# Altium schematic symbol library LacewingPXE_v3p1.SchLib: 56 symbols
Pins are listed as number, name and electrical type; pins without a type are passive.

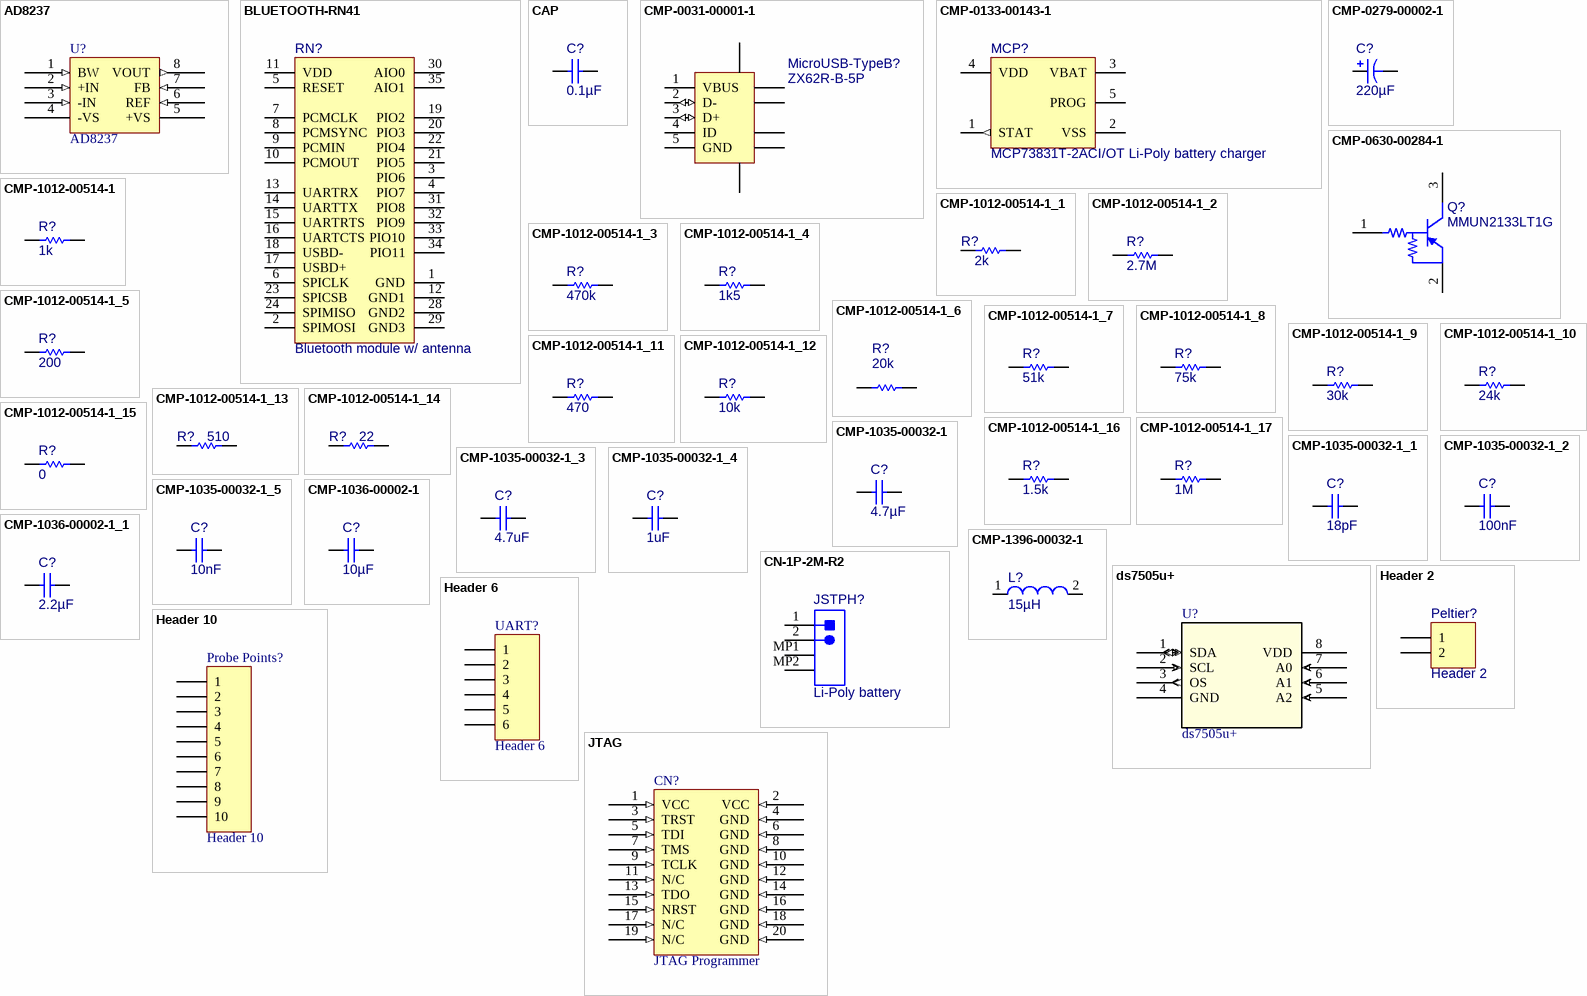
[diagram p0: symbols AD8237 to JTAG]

## AD8237
designator U?
footprint ADI-RM-8_N (SOP, 8-Leads, Body 3x3mm, Pitch 0.65mm, IPC Medium Density)
pins: 1 BW (in), 2 +IN (in), 3 -IN (in), 4 -VS (power), 5 +VS (power), 6 REF (in), 7 FB (in), 8 VOUT (out)

## BLUETOOTH-RN41
designator RN?, comment Bluetooth module w/ antenna
Bluetooth SMD module
footprint RN41
pins: 1 GND, 2 SPIMOSI, 3 PIO6, 4 PIO7, 5 RESET, 6 SPICLK, 7 PCMCLK, 8 PCMSYNC, 9 PCMIN, 10 PCMOUT, 11 VDD, 12 GND1, 13 UARTRX, 14 UARTTX, 15 UARTRTS, 16 UARTCTS, 17 USBD+, 18 USBD-, 19 PIO2, 20 PIO3, 21 PIO5, 22 PIO4, 23 SPICSB, 24 SPIMISO, 28 GND2, 29 GND3, 30 AIO0, 31 PIO8, 32 PIO9, 33 PIO10, 34 PIO11, 35 AIO1

## CAP
designator C?, comment 0.1µF
Ceramic CAP0603 (1608 Metric) Thickness 1mm SMD; Case-EIA: 0603
footprint CAPC0603(1608)100_N (Chip Capacitor, Body 1.6x0.8mm, Height 1.0mm, IPC Medium Density)
pins: 1, 2
1 alternate drawing of the same symbol

## CMP-0031-00001-1
designator MicroUSB-TypeB?, comment ZX62R-B-5P
Connector; USBMicro-B,Reverse type, SMT; 5 Position; Right Angle
footprint HIRO-ZX62R-B-5P_V (USB Micro-B R/A Connector)
pins: 1 VBUS (power), 2 D- (io), 3 D+ (io), 4 ID, 5 GND (power), 6 SHLD, 7 SHLD, 8 SHLD, 9 SHLD, 10 SHLD, 11 SHLD

## CMP-0133-00143-1
designator MCP?, comment MCP73831T-2ACI/OT Li-Poly battery charger
Miniature Single-Cell, Fully Integrated Li-Ion, Li-Polymer Charge Management Controller, 4.2V, 5-Pin SOT-23, Industrial Temperature, Tape and Reel
footprint SOT-23-OT5_M (SOT23, 5-Leads, Body 2.9x1.6mm, Pitch 0.95mm, Lead Span 2.7mm, IPC Low Density)
footprint SOT-23-OT5_L (SOT23, 5-Leads, Body 2.9x1.6mm, Pitch 0.95mm, Lead Span 2.7mm, IPC High Density)
footprint SOT-23-OT5_N (SOT23, 5-Leads, Body 2.9x1.6mm, Pitch 0.95mm, Lead Span 2.7mm, IPC Medium Density)
pins: 1 STAT (out), 2 VSS (power), 3 VBAT (power), 4 VDD (power), 5 PROG

## CMP-0279-00002-1
designator C?, comment 220µF
Capacitor, Tantalum, 220uF 10% 10V MCCT-D (7343-31); PartNumber: TAJD227K010R; Manufacturer: AVX; Polarity: Polarized
footprint AVX-CAPC7343_V (SMT Capacitor, 2 Leads, Body 7.3x4.3mm)
pins: 1, 2

## CMP-0630-00284-1
designator Q?, comment MMUN2133LT1G
Digital Transistor (BRT), R1=4.7 kOhm, R2=47 kOhm, PNP Transistor, 3-Pin SOT-23, Pb-Free, Tape and Reel
footprint ONSC-SOT-23-3-318-08_V (SOT23, 3-Leads, Body 2.92x1.3mm, Pitch 0.95mm)
pins: 1 B, 2 E, 3 C

## CMP-1012-00514-1
designator R?, comment 1k
RES0603 (1608 Metric)  SMD; Case-EIA: 0603
footprint RESC0603(1608)_N (Chip Resistor, Body 1.6x0.8mm, IPC Medium Density)
footprint RESC0603(1608)_M (Chip Resistor, Body 1.6x0.8mm, IPC Low Density)
footprint RESC0603(1608)_L (Chip Resistor, Body 1.6x0.8mm, IPC High Density)
pins: 1, 2
1 alternate drawing of the same symbol

## CMP-1012-00514-1_1
designator R?, comment 2k
RES0603 (1608 Metric)  SMD; Case-EIA: 0603
footprint RESC0603(1608)_N (Chip Resistor, Body 1.6x0.8mm, IPC Medium Density)
footprint RESC0603(1608)_M (Chip Resistor, Body 1.6x0.8mm, IPC Low Density)
footprint RESC0603(1608)_L (Chip Resistor, Body 1.6x0.8mm, IPC High Density)
pins: 1, 2
1 alternate drawing of the same symbol

## CMP-1012-00514-1_2
designator R?, comment 2.7M
RES0603 (1608 Metric)  SMD; Case-EIA: 0603
footprint RESC0603(1608)_N (Chip Resistor, Body 1.6x0.8mm, IPC Medium Density)
footprint RESC0603(1608)_M (Chip Resistor, Body 1.6x0.8mm, IPC Low Density)
footprint RESC0603(1608)_L (Chip Resistor, Body 1.6x0.8mm, IPC High Density)
pins: 1, 2
1 alternate drawing of the same symbol

## CMP-1012-00514-1_3
designator R?, comment 470k
RES0603 (1608 Metric)  SMD; Case-EIA: 0603
footprint RESC0603(1608)_N (Chip Resistor, Body 1.6x0.8mm, IPC Medium Density)
footprint RESC0603(1608)_M (Chip Resistor, Body 1.6x0.8mm, IPC Low Density)
footprint RESC0603(1608)_L (Chip Resistor, Body 1.6x0.8mm, IPC High Density)
pins: 1, 2
1 alternate drawing of the same symbol

## CMP-1012-00514-1_4
designator R?, comment 1k5
RES0603 (1608 Metric)  SMD; Case-EIA: 0603
footprint RESC0603(1608)_N (Chip Resistor, Body 1.6x0.8mm, IPC Medium Density)
footprint RESC0603(1608)_M (Chip Resistor, Body 1.6x0.8mm, IPC Low Density)
footprint RESC0603(1608)_L (Chip Resistor, Body 1.6x0.8mm, IPC High Density)
pins: 1, 2
1 alternate drawing of the same symbol

## CMP-1012-00514-1_5
designator R?, comment 200
RES0603 (1608 Metric)  SMD; Case-EIA: 0603
footprint RESC0603(1608)_N (Chip Resistor, Body 1.6x0.8mm, IPC Medium Density)
footprint RESC0603(1608)_M (Chip Resistor, Body 1.6x0.8mm, IPC Low Density)
footprint RESC0603(1608)_L (Chip Resistor, Body 1.6x0.8mm, IPC High Density)
pins: 1, 2
1 alternate drawing of the same symbol

## CMP-1012-00514-1_6
designator R?, comment 20k
RES0603 (1608 Metric)  SMD; Case-EIA: 0603
footprint RESC0603(1608)_N (Chip Resistor, Body 1.6x0.8mm, IPC Medium Density)
footprint RESC0603(1608)_M (Chip Resistor, Body 1.6x0.8mm, IPC Low Density)
footprint RESC0603(1608)_L (Chip Resistor, Body 1.6x0.8mm, IPC High Density)
pins: 1, 2
1 alternate drawing of the same symbol

## CMP-1012-00514-1_7
designator R?, comment 51k
RES0603 (1608 Metric)  SMD; Case-EIA: 0603
footprint RESC0603(1608)_N (Chip Resistor, Body 1.6x0.8mm, IPC Medium Density)
footprint RESC0603(1608)_M (Chip Resistor, Body 1.6x0.8mm, IPC Low Density)
footprint RESC0603(1608)_L (Chip Resistor, Body 1.6x0.8mm, IPC High Density)
pins: 1, 2
1 alternate drawing of the same symbol

## CMP-1012-00514-1_8
designator R?, comment 75k
RES0603 (1608 Metric)  SMD; Case-EIA: 0603
footprint RESC0603(1608)_N (Chip Resistor, Body 1.6x0.8mm, IPC Medium Density)
footprint RESC0603(1608)_M (Chip Resistor, Body 1.6x0.8mm, IPC Low Density)
footprint RESC0603(1608)_L (Chip Resistor, Body 1.6x0.8mm, IPC High Density)
pins: 1, 2
1 alternate drawing of the same symbol

## CMP-1012-00514-1_9
designator R?, comment 30k
RES0603 (1608 Metric)  SMD; Case-EIA: 0603
footprint RESC0603(1608)_N (Chip Resistor, Body 1.6x0.8mm, IPC Medium Density)
footprint RESC0603(1608)_M (Chip Resistor, Body 1.6x0.8mm, IPC Low Density)
footprint RESC0603(1608)_L (Chip Resistor, Body 1.6x0.8mm, IPC High Density)
pins: 1, 2
1 alternate drawing of the same symbol

## CMP-1012-00514-1_10
designator R?, comment 24k
RES0603 (1608 Metric)  SMD; Case-EIA: 0603
footprint RESC0603(1608)_N (Chip Resistor, Body 1.6x0.8mm, IPC Medium Density)
footprint RESC0603(1608)_M (Chip Resistor, Body 1.6x0.8mm, IPC Low Density)
footprint RESC0603(1608)_L (Chip Resistor, Body 1.6x0.8mm, IPC High Density)
pins: 1, 2
1 alternate drawing of the same symbol

## CMP-1012-00514-1_11
designator R?, comment 470
RES0603 (1608 Metric)  SMD; Case-EIA: 0603
footprint RESC0603(1608)_N (Chip Resistor, Body 1.6x0.8mm, IPC Medium Density)
footprint RESC0603(1608)_M (Chip Resistor, Body 1.6x0.8mm, IPC Low Density)
footprint RESC0603(1608)_L (Chip Resistor, Body 1.6x0.8mm, IPC High Density)
pins: 1, 2
1 alternate drawing of the same symbol

## CMP-1012-00514-1_12
designator R?, comment 10k
RES0603 (1608 Metric)  SMD; Case-EIA: 0603
footprint RESC0603(1608)_N (Chip Resistor, Body 1.6x0.8mm, IPC Medium Density)
footprint RESC0603(1608)_M (Chip Resistor, Body 1.6x0.8mm, IPC Low Density)
footprint RESC0603(1608)_L (Chip Resistor, Body 1.6x0.8mm, IPC High Density)
pins: 1, 2
1 alternate drawing of the same symbol

## CMP-1012-00514-1_13
designator R?, comment 510
RES0603 (1608 Metric)  SMD; Case-EIA: 0603
footprint RESC0603(1608)_N (Chip Resistor, Body 1.6x0.8mm, IPC Medium Density)
footprint RESC0603(1608)_M (Chip Resistor, Body 1.6x0.8mm, IPC Low Density)
footprint RESC0603(1608)_L (Chip Resistor, Body 1.6x0.8mm, IPC High Density)
pins: 1, 2
1 alternate drawing of the same symbol

## CMP-1012-00514-1_14
designator R?, comment 22
RES0603 (1608 Metric)  SMD; Case-EIA: 0603
footprint RESC0603(1608)_N (Chip Resistor, Body 1.6x0.8mm, IPC Medium Density)
footprint RESC0603(1608)_M (Chip Resistor, Body 1.6x0.8mm, IPC Low Density)
footprint RESC0603(1608)_L (Chip Resistor, Body 1.6x0.8mm, IPC High Density)
pins: 1, 2
1 alternate drawing of the same symbol

## CMP-1012-00514-1_15
designator R?, comment 0
RES0603 (1608 Metric)  SMD; Case-EIA: 0603
footprint RESC0603(1608)_N (Chip Resistor, Body 1.6x0.8mm, IPC Medium Density)
footprint RESC0603(1608)_M (Chip Resistor, Body 1.6x0.8mm, IPC Low Density)
footprint RESC0603(1608)_L (Chip Resistor, Body 1.6x0.8mm, IPC High Density)
pins: 1, 2
1 alternate drawing of the same symbol

## CMP-1012-00514-1_16
designator R?, comment 1.5k
RES0603 (1608 Metric)  SMD; Case-EIA: 0603
footprint RESC0603(1608)_N (Chip Resistor, Body 1.6x0.8mm, IPC Medium Density)
footprint RESC0603(1608)_M (Chip Resistor, Body 1.6x0.8mm, IPC Low Density)
footprint RESC0603(1608)_L (Chip Resistor, Body 1.6x0.8mm, IPC High Density)
pins: 1, 2
1 alternate drawing of the same symbol

## CMP-1012-00514-1_17
designator R?, comment 1M
RES0603 (1608 Metric)  SMD; Case-EIA: 0603
footprint RESC0603(1608)_N (Chip Resistor, Body 1.6x0.8mm, IPC Medium Density)
footprint RESC0603(1608)_M (Chip Resistor, Body 1.6x0.8mm, IPC Low Density)
footprint RESC0603(1608)_L (Chip Resistor, Body 1.6x0.8mm, IPC High Density)
pins: 1, 2
1 alternate drawing of the same symbol

## CMP-1035-00032-1
designator C?, comment 4.7µF
Ceramic CAP0603 (1608 Metric) Thickness 1mm SMD; Case-EIA: 0603; Rated Voltage: 10 V
footprint CAPC0603(1608)100_N (Chip Capacitor, Body 1.6x0.8mm, Height 1.0mm, IPC Medium Density)
footprint CAPC0603(1608)100_L (Chip Capacitor, Body 1.6x0.8mm, Height 1.0mm, IPC High Density)
footprint CAPC0603(1608)100_M (Chip Capacitor, Body 1.6x0.8mm, Height 1.0mm, IPC Low Density)
pins: 1, 2
1 alternate drawing of the same symbol

## CMP-1035-00032-1_1
designator C?, comment 18pF
Ceramic CAP0603 (1608 Metric) Thickness 1mm SMD; Case-EIA: 0603
footprint CAPC0603(1608)100_N (Chip Capacitor, Body 1.6x0.8mm, Height 1.0mm, IPC Medium Density)
footprint CAPC0603(1608)100_L (Chip Capacitor, Body 1.6x0.8mm, Height 1.0mm, IPC High Density)
footprint CAPC0603(1608)100_M (Chip Capacitor, Body 1.6x0.8mm, Height 1.0mm, IPC Low Density)
pins: 1, 2
1 alternate drawing of the same symbol

## CMP-1035-00032-1_2
designator C?, comment 100nF
Ceramic CAP0603 (1608 Metric) Thickness 1mm SMD; Case-EIA: 0603
footprint CAPC0603(1608)100_N (Chip Capacitor, Body 1.6x0.8mm, Height 1.0mm, IPC Medium Density)
footprint CAPC0603(1608)100_L (Chip Capacitor, Body 1.6x0.8mm, Height 1.0mm, IPC High Density)
footprint CAPC0603(1608)100_M (Chip Capacitor, Body 1.6x0.8mm, Height 1.0mm, IPC Low Density)
pins: 1, 2
1 alternate drawing of the same symbol

## CMP-1035-00032-1_3
designator C?, comment 4.7uF
Ceramic CAP0603 (1608 Metric) Thickness 1mm SMD; Case-EIA: 0603
footprint CAPC0603(1608)100_N (Chip Capacitor, Body 1.6x0.8mm, Height 1.0mm, IPC Medium Density)
footprint CAPC0603(1608)100_L (Chip Capacitor, Body 1.6x0.8mm, Height 1.0mm, IPC High Density)
footprint CAPC0603(1608)100_M (Chip Capacitor, Body 1.6x0.8mm, Height 1.0mm, IPC Low Density)
pins: 1, 2
1 alternate drawing of the same symbol

## CMP-1035-00032-1_4
designator C?, comment 1uF
Ceramic CAP0603 (1608 Metric) Thickness 1mm SMD; Case-EIA: 0603
footprint CAPC0603(1608)100_N (Chip Capacitor, Body 1.6x0.8mm, Height 1.0mm, IPC Medium Density)
footprint CAPC0603(1608)100_L (Chip Capacitor, Body 1.6x0.8mm, Height 1.0mm, IPC High Density)
footprint CAPC0603(1608)100_M (Chip Capacitor, Body 1.6x0.8mm, Height 1.0mm, IPC Low Density)
pins: 1, 2
1 alternate drawing of the same symbol

## CMP-1035-00032-1_5
designator C?, comment 10nF
Ceramic CAP0603 (1608 Metric) Thickness 1mm SMD; Case-EIA: 0603
footprint CAPC0603(1608)100_N (Chip Capacitor, Body 1.6x0.8mm, Height 1.0mm, IPC Medium Density)
footprint CAPC0603(1608)100_L (Chip Capacitor, Body 1.6x0.8mm, Height 1.0mm, IPC High Density)
footprint CAPC0603(1608)100_M (Chip Capacitor, Body 1.6x0.8mm, Height 1.0mm, IPC Low Density)
pins: 1, 2
1 alternate drawing of the same symbol

## CMP-1036-00002-1
designator C?, comment 10µF
Ceramic CAP0805 (2012 Metric) Thickness 0.75mm SMD; Case-EIA: 0805; Rated Voltage: 10 V
footprint CAPC0805(2012)75_N (Chip Capacitor, Body 2.0x1.2mm, Height 0.75mm, IPC Medium Density)
footprint CAPC0805(2012)75_L (Chip Capacitor, Body 2.0x1.2mm, Height 0.75mm, IPC High Density)
footprint CAPC0805(2012)75_M (Chip Capacitor, Body 2.0x1.2mm, Height 0.75mm, IPC Low Density)
pins: 1, 2
1 alternate drawing of the same symbol

## CMP-1036-00002-1_1
designator C?, comment 2.2µF
Ceramic CAP0805 (2012 Metric) Thickness 0.75mm SMD; Case-EIA: 0805; Rated Voltage: 10 V
footprint CAPC0805(2012)75_N (Chip Capacitor, Body 2.0x1.2mm, Height 0.75mm, IPC Medium Density)
footprint CAPC0805(2012)75_L (Chip Capacitor, Body 2.0x1.2mm, Height 0.75mm, IPC High Density)
footprint CAPC0805(2012)75_M (Chip Capacitor, Body 2.0x1.2mm, Height 0.75mm, IPC Low Density)
pins: 1, 2
1 alternate drawing of the same symbol

## CMP-1396-00032-1
designator L?, comment 15µH
SMD-Shielded Power Inductor WE-PD 7447714150, L=15 µH
footprint WE-PD 1050 (SMD Inductor, 2-Leads, Body 10,0x10,0mm)
pins: 1, 2

## CN-1P-2M-R2
designator JSTPH?, comment Li-Poly battery
JST PH 2-pin 2-holder SMD
footprint JST- S2B-PH-SM4-TB(LF)(SN)-2_V (SMD, 2-Leads, Body 7.9x7.6mm, Pitch 2mm)
footprint JST- S2B-PH-SM4-TB(LF)(SN)-2_V (SMD, 2-Leads, Body 7.9x7.6mm, Pitch 2mm)
footprint JST- S2B-PH-SM4-TB(LF)(SN)-2_V (SMD, 2-Leads, Body 7.9x7.6mm, Pitch 2mm)
pins: 1, 2, MP1, MP2

## ds7505u+
designator U?
No Description Available; Vendor: Maxim Integrated Products; Built_By: EMA_UL_Team
footprint 21-0036K
pins: 1 SDA (io), 2 SCL (in), 3 OS (out), 4 GND (power), 5 A2 (in), 6 A1 (in), 7 A0 (in), 8 VDD (power)

## Header 2
designator Peltier?
Header, 2-Pin
footprint HDR1X2 (Connector; Header; 2 Position)
pins: 1, 2

## Header 6
designator UART?
Header, 6-Pin
footprint HDR1X6 (Connector; Header; 6 Position)
signal-integrity model Connector
pins: 1, 2, 3, 4, 5, 6

## Header 10
designator Probe Points?
Header, 10-Pin
footprint HDR1X10 (Connector; Header; 10 Position)
signal-integrity model Connector
pins: 1, 2, 3, 4, 5, 6, 7, 8, 9, 10

## JTAG
designator CN?, comment JTAG Programmer
footprint JTAG (Connector; 20 pin)
footprint JTAG2 (Header, Vertical Shrouded, 100 mil pitch; 25 mil lead width, 20 pins, 2 rows, 10 pins per row, 1295 mil L X 346 mil W X 346 mil H body)
pins: 1 VCC (in), 2 VCC (in), 3 TRST (in), 4 GND (in), 5 TDI (in), 6 GND (in), 7 TMS (in), 8 GND (in), 9 TCLK (in), 10 GND (in), 11 N/C (in), 12 GND (in), 13 TDO (in), 14 GND (in), 15 NRST (in), 16 GND (in), 17 N/C (in), 18 GND (in), 19 N/C (in), 20 GND (in)

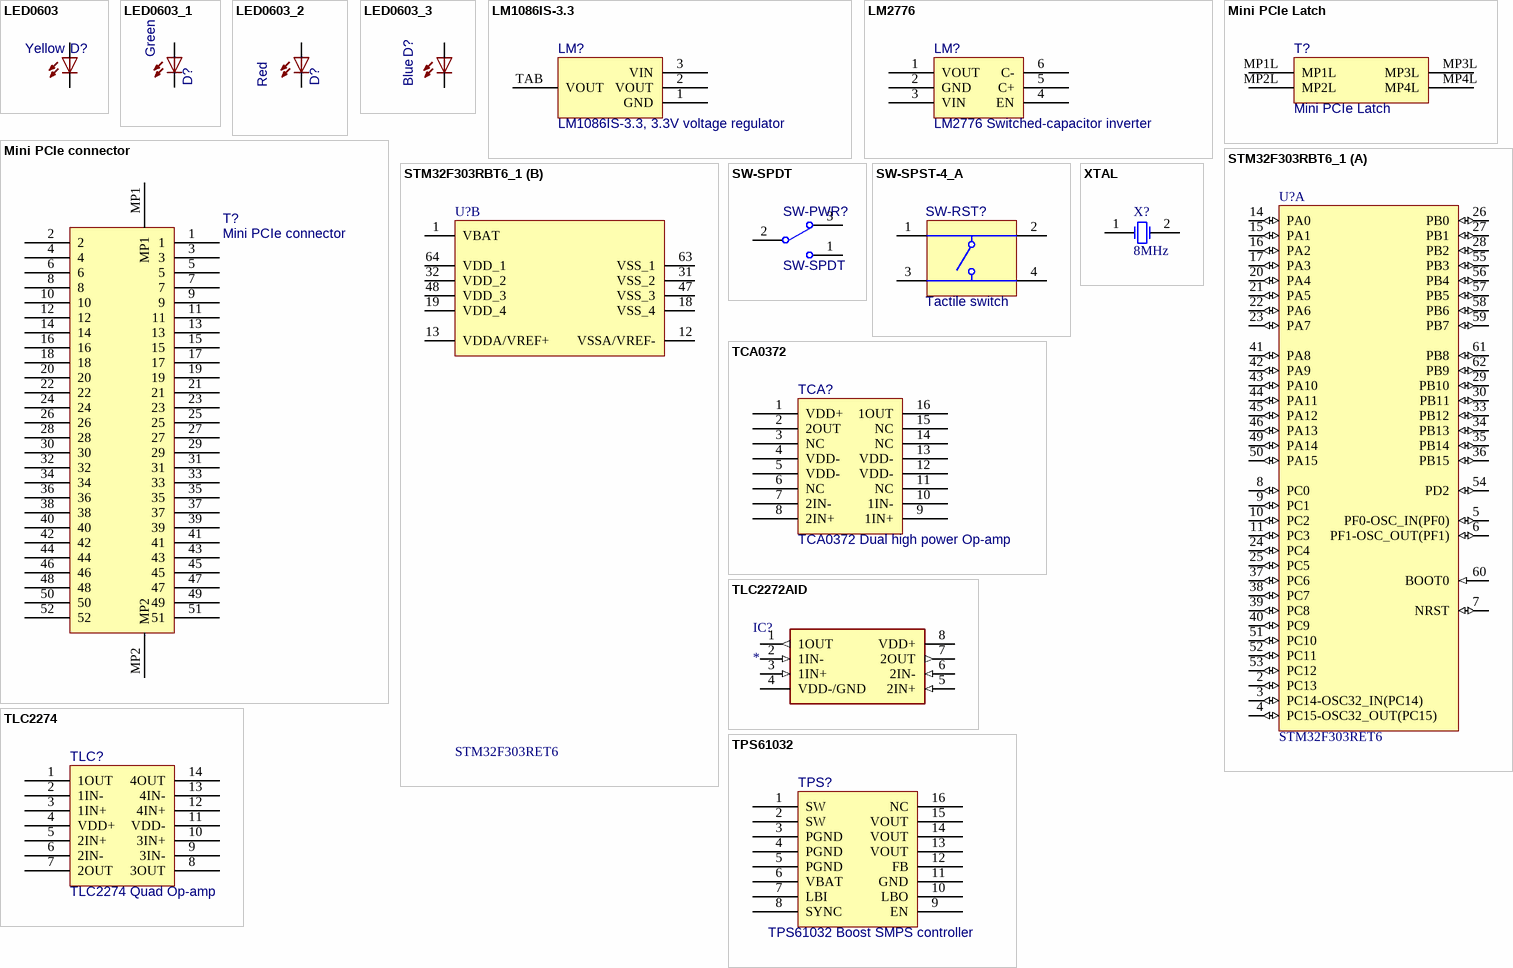
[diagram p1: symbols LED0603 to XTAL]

## LED0603
designator D?, comment Yellow
LED SMD 0603
footprint LED-0603
pins: A, C

## LED0603_1
designator D?, comment Green
LED SMD 0603
footprint LED-0603
pins: A, C

## LED0603_2
designator D?, comment Red
LED SMD 0603
footprint LED-0603
pins: A, C

## LED0603_3
designator D?, comment Blue
LED SMD 0603; RS Order: 654-5666
footprint LED-0603
pins: A, C

## LM1086IS-3.3
designator LM?, comment LM1086IS-3.3, 3.3V voltage regulator
footprint TS3B_M (D2-PAK, 4-Leads, Body 8.6x10.2mm, Pitch 2.54mm, Lead Span 14.2mm, IPC Low Density)
pins: 1 GND, 2 VOUT, 3 VIN, TAB VOUT

## LM2776
designator LM?, comment LM2776 Switched-capacitor inverter
footprint TI-DBV6_M (SOT-23, 6-Leads, Body 2.90x1.60mm, Pitch 0.95mm, IPC Low Density)
pins: 1 VOUT, 2 GND, 3 VIN, 4 EN, 5 C+, 6 C-

## Mini PCIe connector
designator T?
footprint Molex Conn-67910 (Board-to-Board Connector, SMT, Right Angle, Pitch 0.8mm, 52-Position, Female)
pins: 1, 2, 3, 4, 5, 6, 7, 8, 9, 10, 11, 12, 13, 14, 15, 16, 17, 18, 19, 20, 21, 22, 23, 24, 25, 26, 27, 28, 29, 30, 31, 32, 33, 34, 35, 36, 37, 38, 39, 40, 41, 42, 43, 44, 45, 46, 47, 48, 49, 50, 51, 52, MP1, MP2

## Mini PCIe Latch
designator T?
footprint Molex Latch-48099
pins: MP1L, MP2L, MP3L, MP4L

## STM32F303RBT6_1
designator U?, comment STM32F303RET6
ARM Cortex-M4 32-bit MCU, 128 KB Flash, 32 KB Internal RAM, 52 I/Os, 64-pin LQFP, -40 to 85 degC, Tray; PartNumber: STM32F303RBT6; D/A Converter: 2x12-bit (2 Channel); FLASH Size (Prog) (kB): 128; I/Os (High Current): 52; Internal RAM Size (kB): 32; Operating Frequency(F) (Processor speed) (MHz): 72; Supply Voltage(Vcc) min (V): 2
footprint STM-LQFP64_N (Thin QFP, 64-Leads, Body 10x10mm, Pitch 0.5mm, IPC Medium Density)
footprint STM-LQFP64_L (Thin QFP, 64-Leads, Body 10x10mm, Pitch 0.5mm, IPC High Density)
footprint STM-LQFP64_M (Thin QFP, 64-Leads, Body 10x10mm, Pitch 0.5mm, IPC Low Density)
footprint STM-LQFP64_V (Thin QFP, 64-Leads, Body 10x10mm, Pitch 0.5mm, ST Recommended)
part A pins: 2 PC13 (io) "PC13/TIM1_CH1N/WKUP2,RTC_TAMP1,RTC_TS,RTC_OUT", 3 PC14-OSC32_IN(PC14) (io) "PC14-OSC32_IN(PC14)/OSC32_IN", 4 PC15-OSC32_OUT(PC15) (io) "PC15-OSC32_OUT(PC15)/OSC32_OUT", 5 PF0-OSC_IN(PF0) (io) "PF0-OSC_IN(PF0)/TIM1_CH3N,I2C2_SDA/OSC_IN", 6 PF1-OSC_OUT(PF1) (io) "PF1-OSC_OUT(PF1)/I2C2_SCL/OSC_OUT", 7 NRST (io) "Device reset input / internal reset output (active low)", 8 PC0 (io) "PC0/EVENTOUT/ADC12_IN6,COMP7_INM", 9 PC1 (io) "PC1/EVENTOUT/ADC12_IN7,COMP7_INP", 10 PC2 (io) "PC2/COMP7_OUT,EVENTOUT/ADC12_IN8", 11 PC3 (io) "PC3/TIM1_BKIN2,EVENTOUT/ADC12_IN9", 14 PA0 (io) "PA0/USART2_CTS,TIM2_CH1_ETR,TIM8_BKIN,TIM8_ETR,TSC_G1_IO1,COMP1_OUT,EVENTOUT/ADC1_IN1,COMP1_INM,RTC_TAMP2,WKUP1,COMP7_INP", 15 PA1 (io) "PA1/USART2_RTS,TIM2_CH2,TSC_G1_IO2,TIM15_CH1N,RTC_REFIN,EVENTOUT/ADC1_IN2,COMP1_INP,OPAMP1_VINP,OPAMP3_VINP", 16 PA2 (io) "PA2/USART2_TX,TIM2_CH3,TIM15_CH1,TSC_G1_IO3,COMP2_OUT,EVENTOUT/ADC1_IN3,COMP2_INM,OPAMP1_VOUT", 17 PA3 (io) "PA3/USART2_RX,TIM2_CH4,TIM15_CH2,TSC_G1_IO4,EVENTOUT/ADC1_IN4,OPAMP1_VINP,COMP2_INP,OPAMP1_VINM", 20 PA4 (io) "PA4/SPI1_NSS,SPI3_NSS,I2S3_WS,USART2_CK,TSC_G2_IO1,TIM3_CH2,EVENTOUT/ADC2_IN1,DAC1_OUT1,OPAMP4_VINP,COMP1_INM,COMP2_INM,COMP3_INM,COMP4_INM,COMP5_INM,COMP6_INM,COMP7_INM", 21 PA5 (io) "PA5/SPI1_SCK,TIM2_CH1_ETR,TSC_G2_IO2,EVENTOUT/ADC2_IN2,DAC1_OUT2,OPAMP1_VINP,OPAMP2_VINM,OPAMP3_VINP,COMP1_INM,COMP2_INM,COMP3_INM,COMP4_INM,COMP5_INM,COMP6_INM,COMP7_INM", 22 PA6 (io) "PA6/SPI1_MISO,TIM3_CH1,TIM8_BKIN,TIM1_BKIN,TIM16_CH1,COMP1_OUT,TSC_G2_IO3,EVENTOUT/ADC2_IN3,OPAMP2_VOUT", 23 PA7 (io) "PA7/SPI1_MOSI,TIM3_CH2,TIM17_CH1,TIM1_CH1N,TIM8_CH1N,TSC_G2_IO4,COMP2_OUT,EVENTOUT/ADC2_IN4,COMP2_INP,OPAMP2_VINP,OPAMP1_VINP", 24 PC4 (io) "PC4/USART1_TX,EVENTOUT/ADC2_IN5", 25 PC5 (io) "PC5/USART1_RX,TSC_G3_IO1,EVENTOUT/ADC2_IN11,OPAMP2_VINM,OPAMP1_VINM", 26 PB0 (io) "PB0/TIM3_CH3,TIM1_CH2N,TIM8_CH2N,TSC_G3_IO2,EVENTOUT/ADC3_IN12,COMP4_INP,OPAMP3_VINP,OPAMP2_VINP", 27 PB1 (io) "PB1/TIM3_CH4,TIM1_CH3N,TIM8_CH3N,COMP4_OUT,TSC_G3_IO3,EVENTOUT/ADC3_IN1,OPAMP3_VOUT", 28 PB2 (io) "PB2/TSC_G3_IO4,EVENTOUT/ADC2_IN12,COMP4_INM,OPAMP3_VINM", 29 PB10 (io) "PB10/USART3_TX,TIM2_CH3,TSC_SYNC,EVENTOUT/COMP5_INM,OPAMP4_VINM,OPAMP3_VINM", 30 PB11 (io) "PB11/USART3_RX,TIM2_CH4,TSC_G6_IO1,EVENTOUT/COMP6_INP,OPAMP4_VINP", 33 PB12 (io) "PB12/SPI2_NSS,I2S2_WS,I2C2_SMBA,USART3_CK,TIM1_BKIN,TSC_G6_IO2,EVENTOUT/ADC4_IN3,COMP3_INM,OPAMP4_VOUT", 34 PB13 (io) "PB13/SPI2_SCK,I2S2_CK,USART3_CTS,TIM1_CH1N,TSC_G6_IO3,EVENTOUT/ADC3_IN5,COMP5_INP,OPAMP4_VINP,OPAMP3_VINP", 35 PB14 (io) "PB14/SPI2_MISO,I2S2ext_SD,USART3_RTS,TIM1_CH2N,TIM15_CH1,TSC_G6_IO4,EVENTOUT/COMP3_INP,ADC4_IN4,OPAMP2_VINP", 36 PB15 (io) "PB15/SPI2_MOSI,I2S2_SD,TIM1_CH3N,RTC_REFIN,TIM15_CH1N,TIM15_CH2,EVENTOUT/ADC4_IN5,COMP6_INM", 37 PC6 (io) "PC6/I2S2_MCK,COMP6_OUT,TIM8_CH1,TIM3_CH1,EVENTOUT", 38 PC7 (io) "PC7/I2S3_MCK,TIM8_CH2,TIM3_CH2,COMP5_OUT,EVENTOUT", 39 PC8 (io) "PC8/TIM8_CH3,TIM3_CH3,COMP3_OUT,EVENTOUT", 40 PC9 (io) "PC9/TIM8_CH4,TIM8_BKIN2,TIM3_CH4,I2S_CKIN,EVENTOUT", 41 PA8 (io) "PA8/I2C2_SMBA,I2S2_MCK,USART1_CK,TIM1_CH1,TIM4_ETR,MCO,COMP3_OUT,EVENTOUT", 42 PA9 (io) "PA9/I2C2_SCL,I2S3_MCK,USART1_TX,TIM1_CH2,TIM2_CH3,TIM15_BKIN,TSC_G4_IO1,COMP5_OUT,EVENTOUT", 43 PA10 (io) "PA10/I2C2_SDA,USART1_RX,TIM1_CH3,TIM2_CH4,TIM8_BKIN,TIM17_BKIN,TSC_G4_IO2,COMP6_OUT,EVENTOUT", 44 PA11 (io) "PA11/USART1_CTS,USB_DM,CAN_RX,TIM1_CH1N,TIM1_CH4,TIM1_BKIN2,TIM4_CH1,COMP1_OUT,EVENTOUT", 45 PA12 (io) "PA12/USART1_RTS,USB_DP,CAN_TX,TIM1_CH2N,TIM1_ETR,TIM4_CH2,TIM16_CH1,COMP2_OUT,EVENTOUT", 46 PA13 (io) "PA13/USART3_CTS,TIM4_CH3,TIM16_CH1N,TSC_G4_IO3,IR_OUT,SWDIO-JTMS,EVENTOUT", 49 PA14 (io) "PA14/I2C1_SDA,USART2_TX,TIM8_CH2,TIM1_BKIN,TSC_G4_IO4,SWCLK-JTCK,EVENTOUT", 50 PA15 (io) "PA15/I2C1_SCL,SPI1_NSS,SPI3_NSS,I2S3_WS,JTDI,USART2_RX,TIM1_BKIN,TIM2_CH1_ETR,TIM8_CH1,EVENTOUT", 51 PC10 (io) "PC10/SPI3_SCK,I2S3_CK,USART3_TX,UART4_TX,TIM8_CH1N,EVENTOUT", 52 PC11 (io) "PC11/SPI3_MISO,I2S3ext_SD,USART3_RX,UART4_RX,TIM8_CH2N,EVENTOUT", 53 PC12 (io) "PC12/SPI3_MOSI,I2S3_SD,USART3_CK,UART5_TX,TIM8_CH3N,EVENTOUT", 54 PD2 (io) "PD2/UART5_RX,TIM3_ETR,TIM8_BKIN,EVENTOUT", 55 PB3 (io) "PB3/SPI3_SCK,I2S3_CK,SPI1_SCK,USART2_TX,TIM2_CH2,TIM3_ETR,TIM4_ETR,TIM8_CH1N,TSC_G5_IO1,JTDO-TRACESWO,EVENTOUT", 56 PB4 (io) "PB4/SPI3_MISO,I2S3ext_SD,SPI1_MISO,USART2_RX,TIM3_CH1,TIM16_CH1,TIM17_BKIN,TIM8_CH2N,TSC_G5_IO2,NJTRST,EVENTOUT", 57 PB5 (io) "PB5/SPI3_MOSI,SPI1_MOSI,I2S3_SD,I2C1_SMBA,USART2_CK,TIM16_BKIN,TIM3_CH2,TIM8_CH3N,TIM17_CH1,EVENTOUT", 58 PB6 (io) "PB6/I2C1_SCL,USART1_TX,TIM16_CH1N,TIM4_CH1,TIM8_CH1,TSC_G5_IO3,TIM8_ETR,TIM8_BKIN2,EVENTOUT", 59 PB7 (io) "PB7/I2C1_SDA,USART1_RX,TIM3_CH4,TIM4_CH2,TIM17_CH1N,TIM8_BKIN,TSC_G5_IO4,EVENTOUT", 60 BOOT0 (in) "Boot memory selection", 61 PB8 (io) "PB8/I2C1_SCL,CAN_RX,TIM16_CH1,TIM4_CH3,TIM8_CH2,TIM1_BKIN,TSC_SYNC,COMP1_OUT,EVENTOUT", 62 PB9 (io) "PB9/I2C1_SDA,CAN_TX,TIM17_CH1,TIM4_CH4,TIM8_CH3,IR_OUT,COMP2_OUT,EVENTOUT"
part B pins: 1 VBAT (power) "Backup power supply", 12 VSSA/VREF- (power) "Analog ground/Negative reference voltage", 13 VDDA/VREF+ (power) "Analog power supply/Positive reference voltage", 18 VSS_4 (power) "Digital ground", 19 VDD_4 (power) "Digital power supply", 31 VSS_2 (power) "Digital ground", 32 VDD_2 (power) "Digital power supply", 47 VSS_3 (power) "Ground", 48 VDD_3 (power) "Digital power supply", 63 VSS_1 (power) "Ground", 64 VDD_1 (power) "Digital power supply"

## SW-SPDT
designator SW-PWR?
Switch SPDT CS12ANW03
footprint SWITCH SPDT CS12ANW03
pins: 1, 2, 3

## SW-SPST-4_A
designator SW-RST?, comment Tactile switch
ORMON B3F-10XX
footprint OMRON-B3F-1000-4_V (TH, 4-Leads, Body 6x6mm)
pins: 1, 2, 3, 4

## TCA0372
designator TCA?, comment TCA0372 Dual high power Op-amp
footprint ONSC-SOIC-16-751G-03_V (SOIC, 16-Leads, Body 10.45x7.6mm, Pitch 1.27mm)
pins: 1 VDD+, 2 2OUT, 3 NC, 4 VDD-, 5 VDD-, 6 NC, 7 2IN-, 8 2IN+, 9 1IN+, 10 1IN-, 11 NC, 12 VDD-, 13 VDD-, 14 NC, 15 NC, 16 1OUT

## TLC2272AID
designator IC?
Integrated Circuit; Manufacturer_Name: Texas Instruments; Manufacturer_Part_Number: TLC2272AID; Description: Advanced LinCMOS&#153; Rail-To-Rail Dual Operational Amplifier
footprint SOIC127P600X175-8N
pins: 1 1OUT (out), 2 1IN- (in), 3 1IN+ (in), 4 VDD-/GND (power), 5 2IN+ (in), 6 2IN- (in), 7 2OUT (out), 8 VDD+ (power)

## TLC2274
designator TLC?, comment TLC2274 Quad Op-amp
footprint TI-D14_M (SOIC, 14-Leads, Body 8.65x3.9mm, Pitch 1.27mm, IPC Low Density)
pins: 1 1OUT, 2 1IN-, 3 1IN+, 4 VDD+, 5 2IN+, 6 2IN-, 7 2OUT, 8 3OUT, 9 3IN-, 10 3IN+, 11 VDD-, 12 4IN+, 13 4IN-, 14 4OUT

## TPS61032
designator TPS?, comment TPS61032 Boost SMPS controller
footprint PW0016A_M (SOP, 16-Leads, Body 5.1x4.5mm, Pitch 0.65mm, IPC Low Density)
pins: 1 SW, 2 SW, 3 PGND, 4 PGND, 5 PGND, 6 VBAT, 7 LBI, 8 SYNC, 9 EN, 10 LBO, 11 GND, 12 FB, 13 VOUT, 14 VOUT, 15 VOUT, 16 NC

## XTAL
designator X?, comment 8MHz
Crystal Oscillator
footprint R38 (Crystal, Thru-Hole; 2 Leads; Body 3.1 x 8.2 mm (Dia.xH))
simulation model XTAL (Spice Subcircuit)
footprint QCL
pins: 1 OSC1, 2 OSC2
